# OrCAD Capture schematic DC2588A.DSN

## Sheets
1 PAGE2: size B; title: 18-Bit, 15Msps SAR ADC + Driver Amp; rev: 2; company: LTC2387CUH FAMILY; note: DEMO CIRCUIT 2588A; note: B
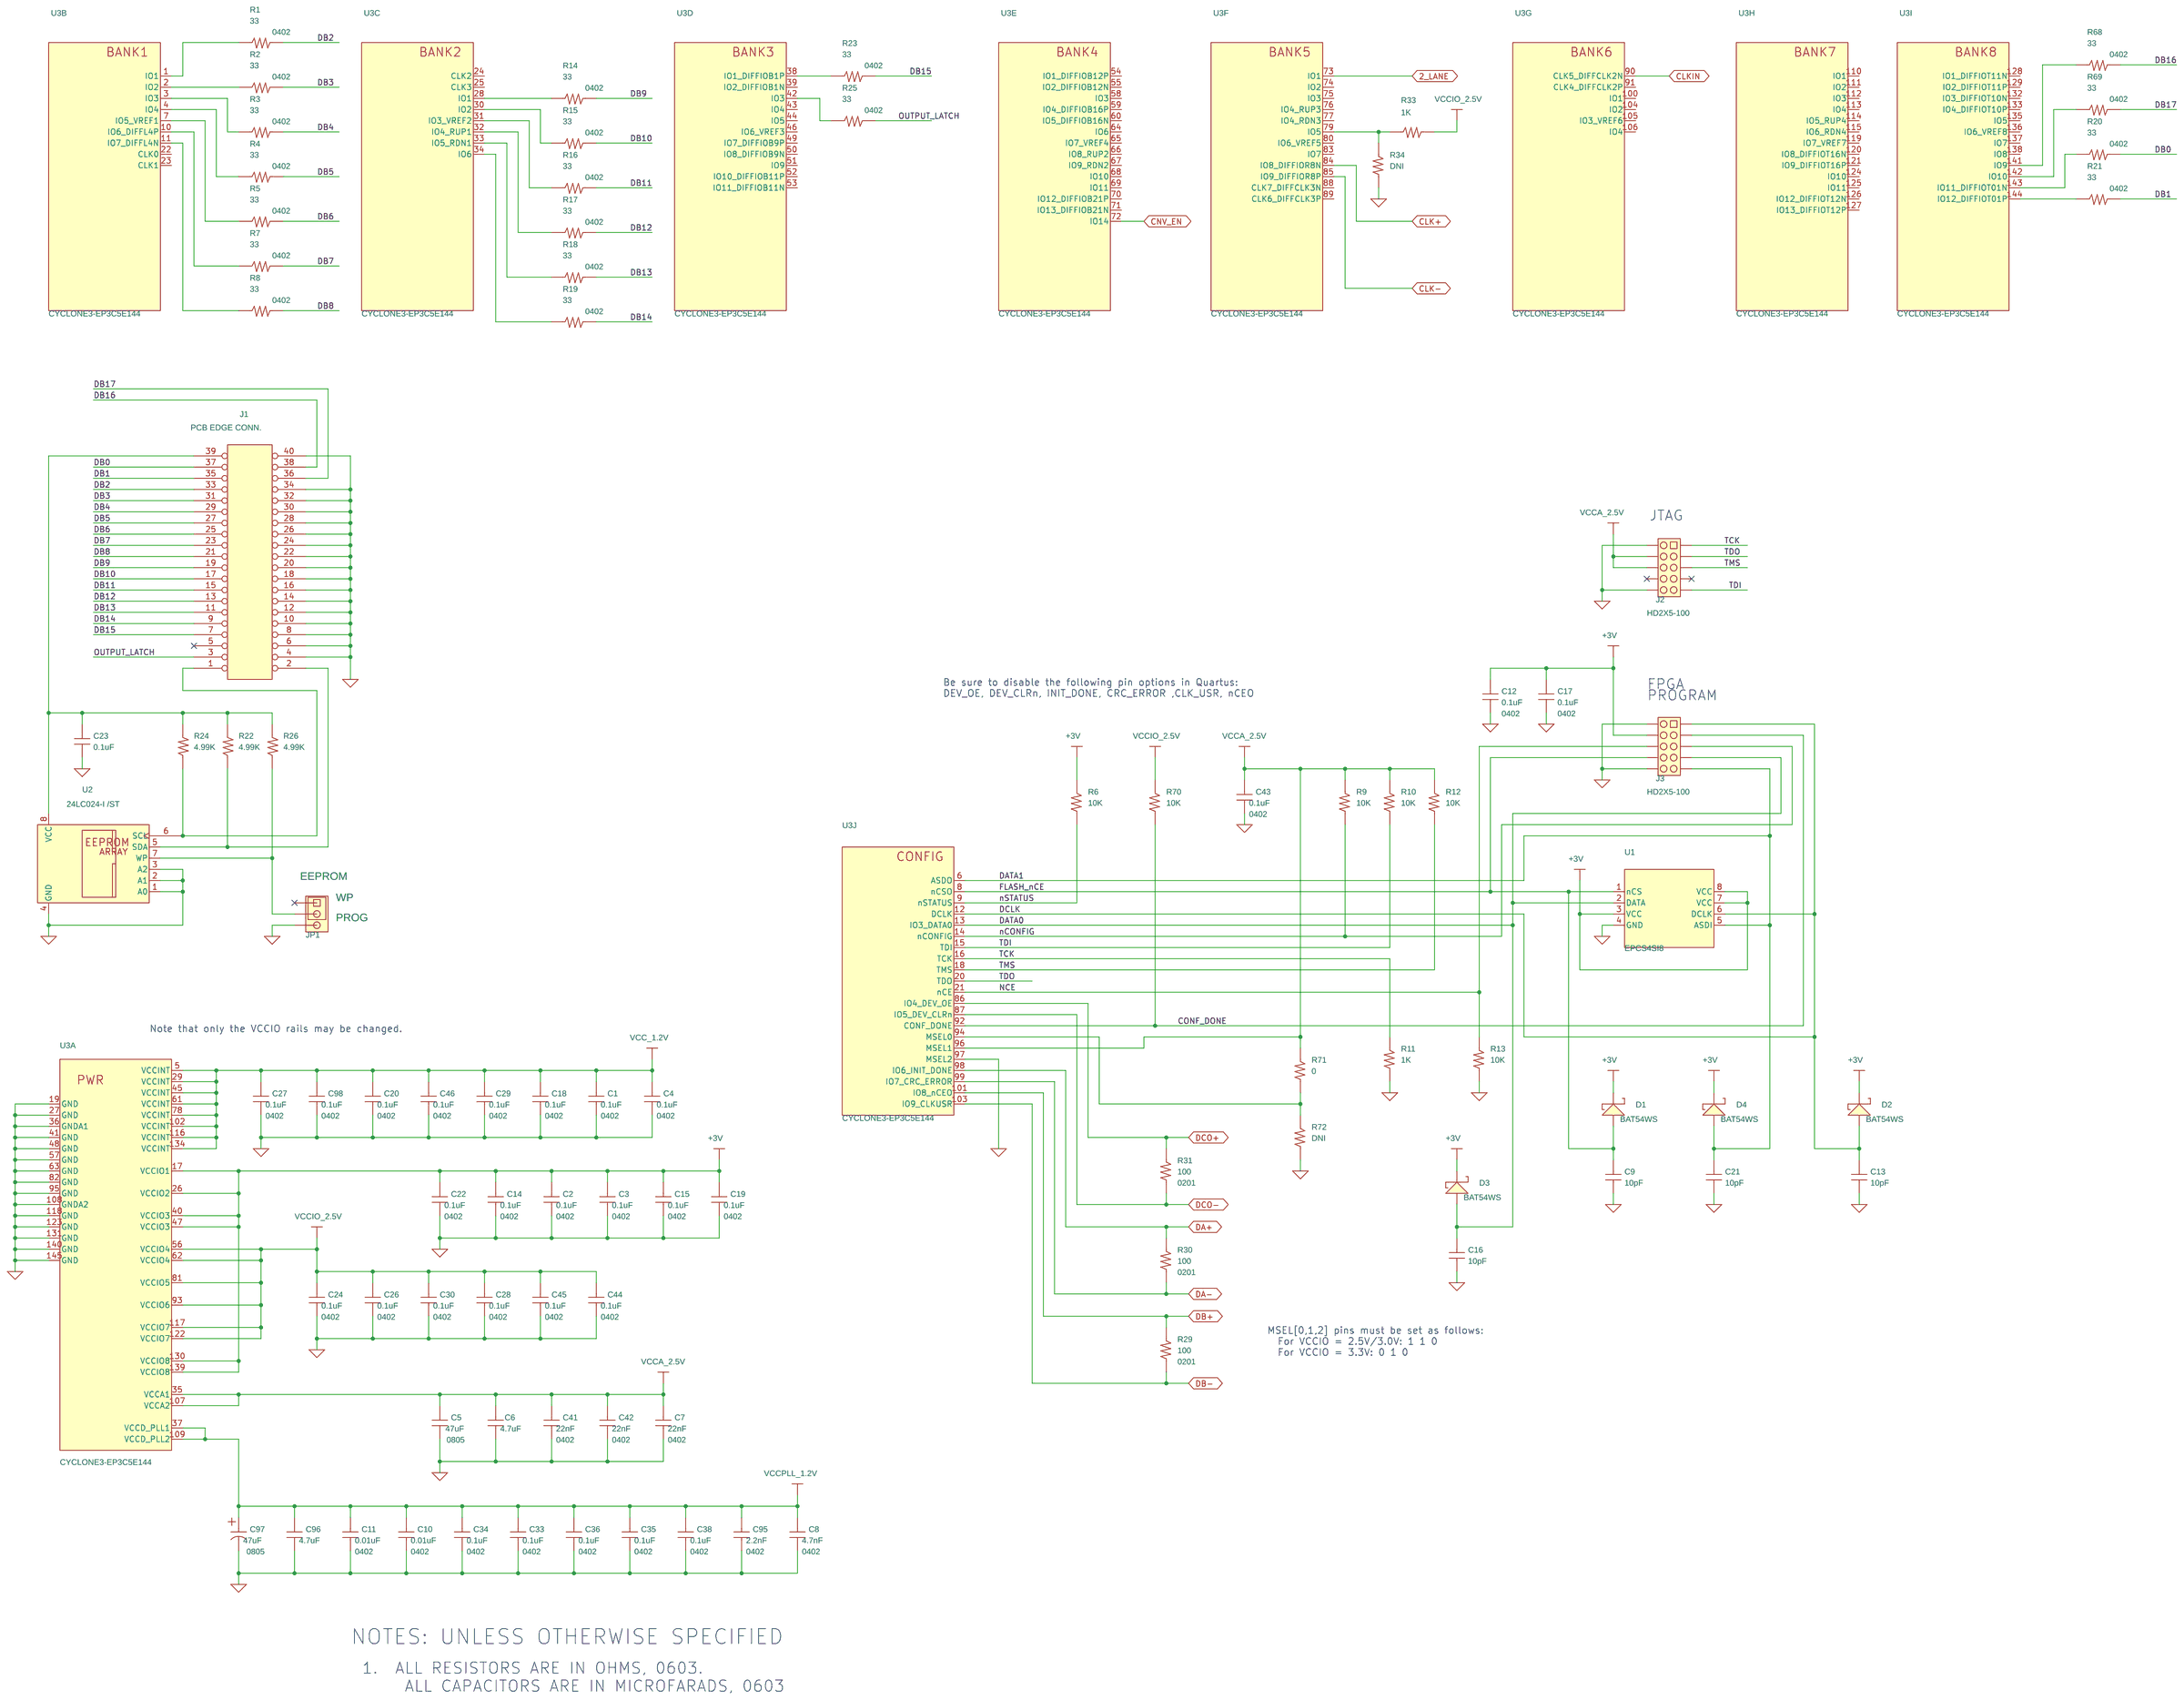
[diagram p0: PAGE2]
2 PAGE1: size B; rev: 1
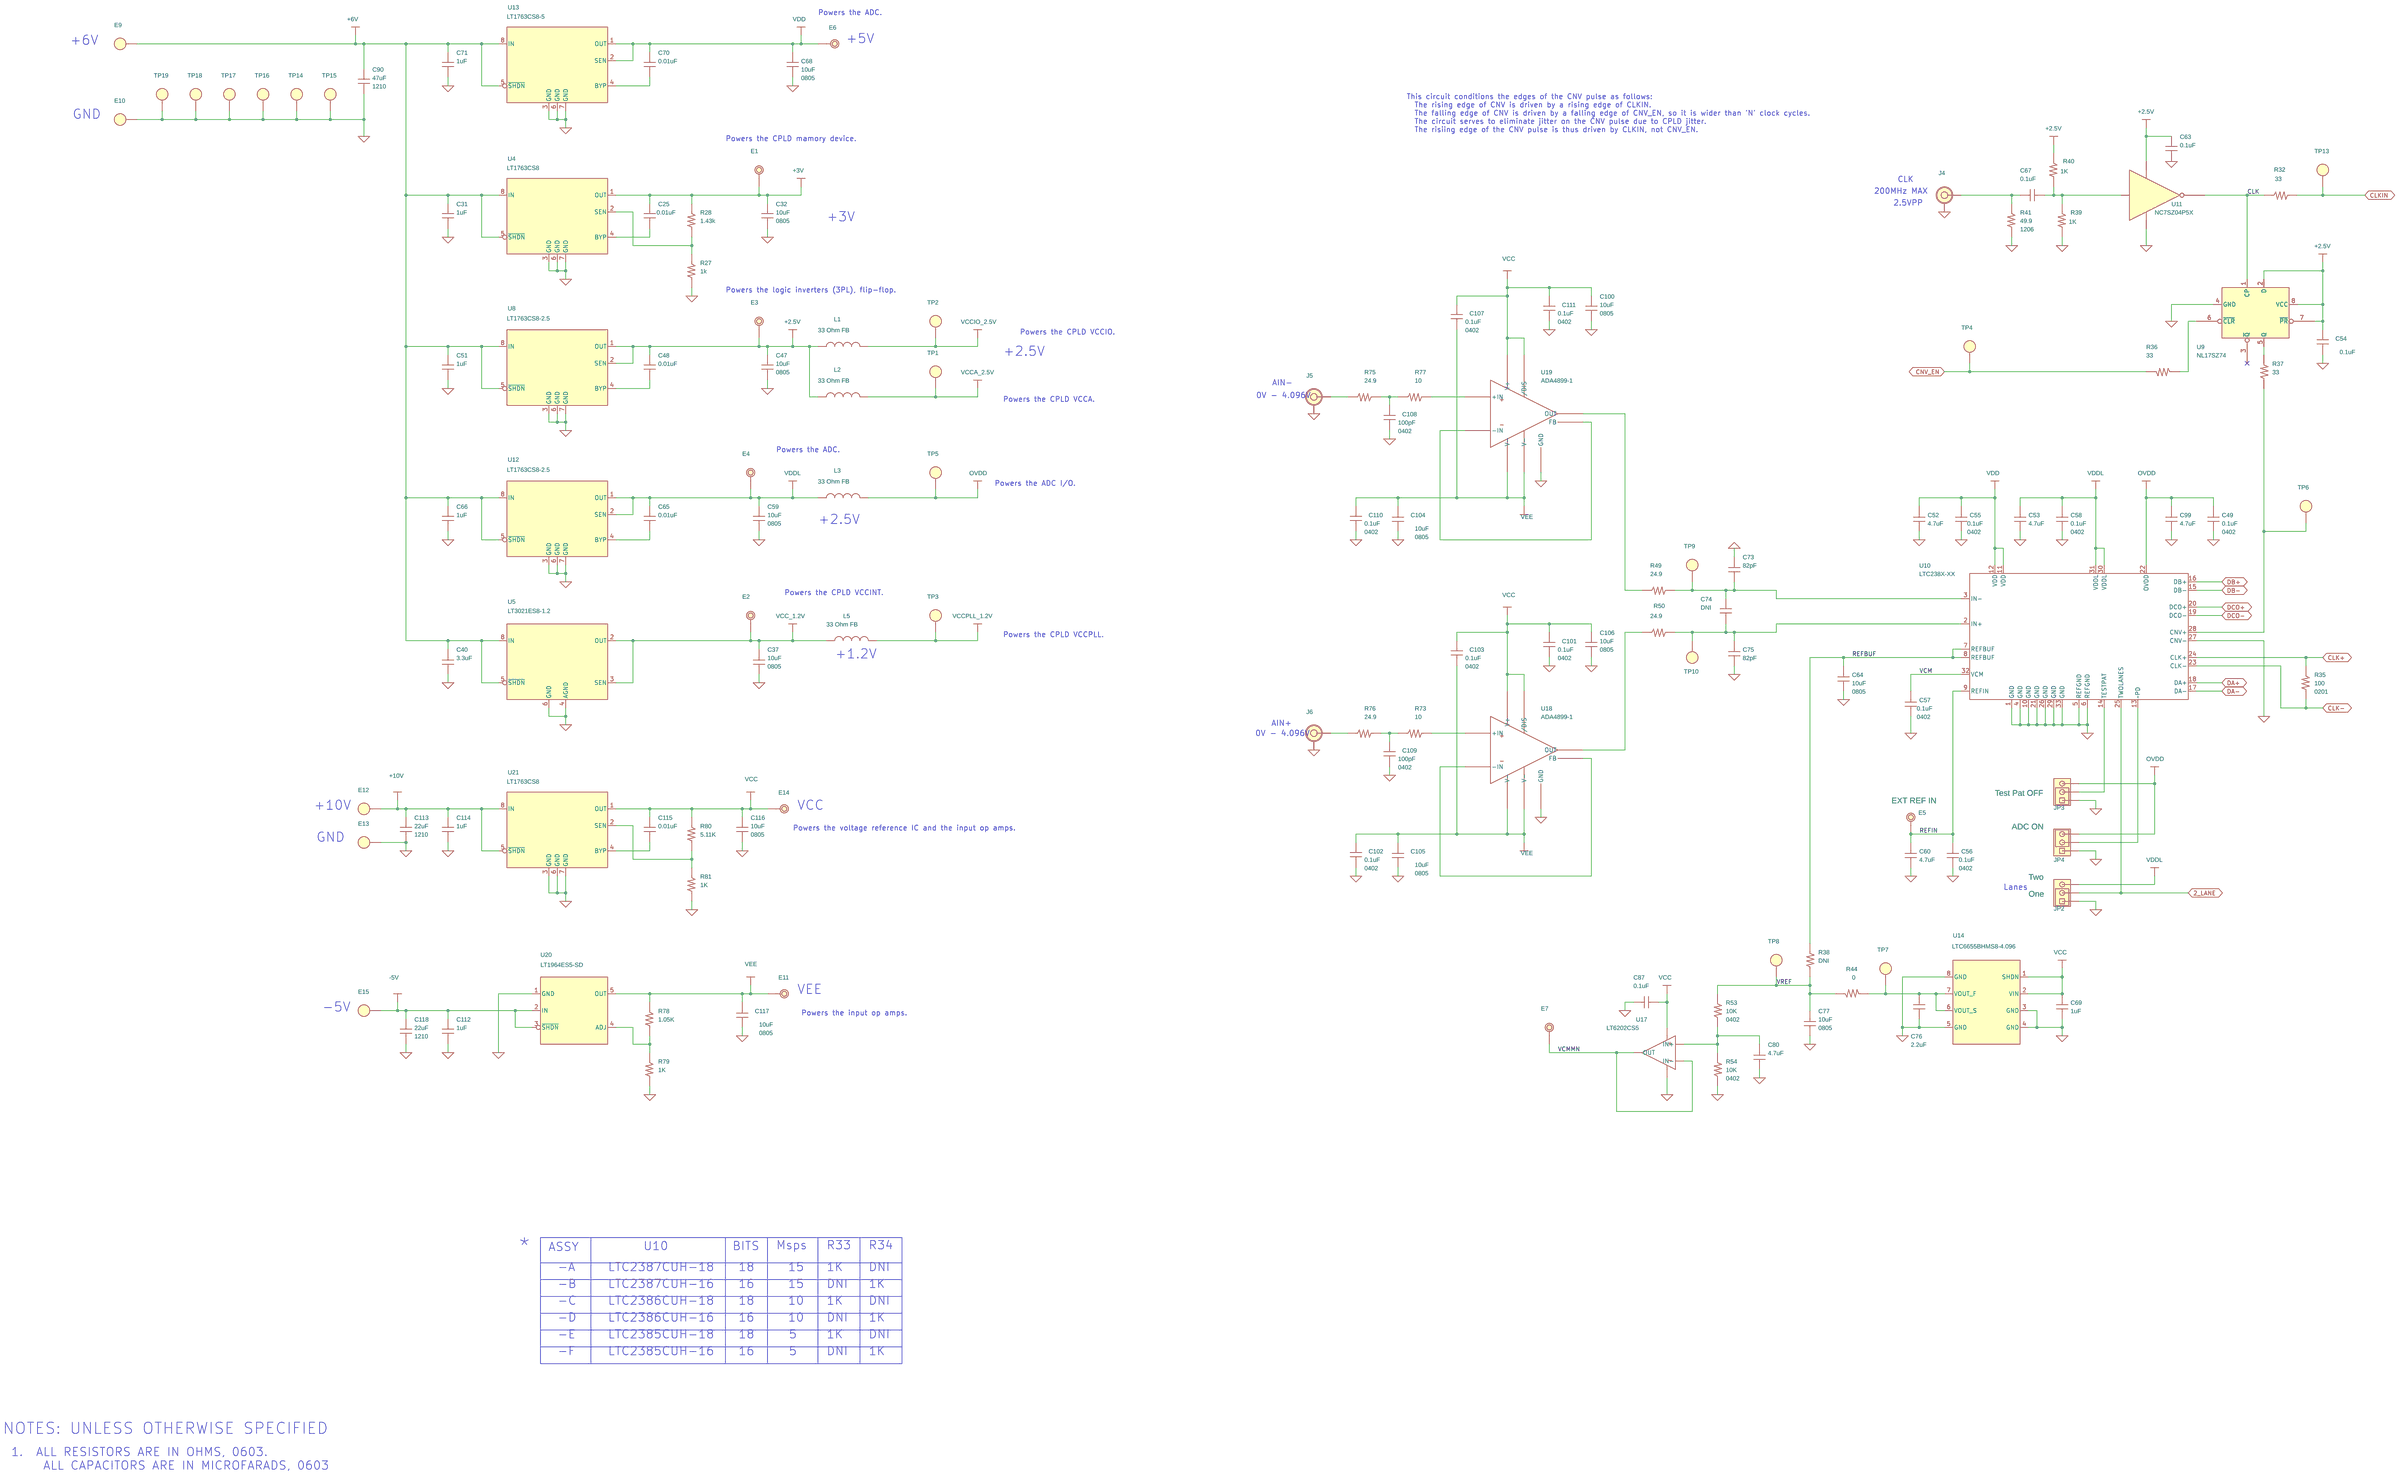
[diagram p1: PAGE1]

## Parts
sheet PAGE1
C25  0.01uF  [0603]
C31  1uF  [0603]
C32  10uF  [0805]
C37  10uF  [0805]
C40  3.3uF  [0603]
C47  10uF  [0805]
C48  0.01uF  [0603]
C49  0.1uF  [0402]
C51  1uF  [0603]
C52  4.7uF  [0603]
C53  4.7uF  [0603]
C54  0.1uF  [0603]
C55  0.1uF  [0402]
C56  0.1uF  [0402]
C57  0.1uF  [0402]
C58  0.1uF  [0402]
C59  10uF  [0805]
C60  4.7uF  [0603]
C63  0.1uF  [0603]
C64  10uF  [0805]
C65  0.01uF  [0603]
C66  1uF  [0603]
C67  0.1uF  [0603]
C68  10uF  [0805]
C69  1uF  [0603]
C70  0.01uF  [0603]
C71  1uF  [0603]
C73  82pF  [0603]
C74  DNI  [0603]
C75  82pF  [0603]
C76  2.2uF  [0603]
C77  10uF  [0805]
C80  4.7uF  [0603]
C87  0.1uF  [0603]
C90  47uF  [1210]
C99  4.7uF  [0603]
C100  10uF  [0805]
C101  0.1uF  [0402]
C102  0.1uF  [0402]
C103  0.1uF  [0402]
C104  10uF  [0805]
C105  10uF  [0805]
C106  10uF  [0805]
C107  0.1uF  [0402]
C108  100pF  [0402]
C109  100pF  [0402]
C110  0.1uF  [0402]
C111  0.1uF  [0402]
C112  1uF  [0603]
C113  22uF  [1210]
C114  1uF  [0603]
C115  0.01uF  [0603]
C116  10uF  [0805]
C117  10uF  [0805]
C118  22uF  [1210]
E1  MILL-MAX-2308  [MILL-MAX-2308]
E2  MILL-MAX-2308  [MILL-MAX-2308]
E3  MILL-MAX-2308  [MILL-MAX-2308]
E4  MILL-MAX-2308  [MILL-MAX-2308]
E5  MILL-MAX-2308  [MILL-MAX-2308]
E6  MILL-MAX-2308  [MILL-MAX-2308]
E7  MILL-MAX-2308  [MILL-MAX-2308]
E9  MIL-MAX-2501  [MILL-MAX-2501]
E10  MIL-MAX-2501  [MILL-MAX-2501]
E11  MILL-MAX-2308  [MILL-MAX-2308]
E12  MIL-MAX-2501  [MILL-MAX-2501]
E13  MIL-MAX-2501  [MILL-MAX-2501]
E14  MILL-MAX-2308  [MILL-MAX-2308]
E15  MIL-MAX-2501  [MILL-MAX-2501]
J4  BNC5  [BNC5]
J5  BNC5  [EFJOHNSON142-0701-851]
J6  BNC5  [EFJOHNSON142-0701-851]
JP2  HD1X3-100  [HD1X3-100]
JP3  HD1X3-100  [HD1X3-100]
JP4  HD1X3-100  [HD1X3-100]
L1  33 Ohm FB  [0603]
L2  33 Ohm FB  [0603]
L3  33 Ohm FB  [0603]
L5  33 Ohm FB  [0603]
R27  1k  [0603]
R28  1.43k  [0603]
R32  33  [0603]
R35  100  [0201]
R36  33  [0603]
R37  33  [0603]
R38  DNI  [0603]
R39  1K  [0603]
R40  1K  [0603]
R41  49.9  [1206]
R44  0  [0603]
R49  24.9  [0402]
R50  24.9  [0402]
R53  10K  [0402]
R54  10K  [0402]
R73  10  [0402]
R75  24.9  [0402]
R76  24.9  [0402]
R77  10  [0402]
R78  1.05K  [0603]
R79  1K  [0603]
R80  5.11K  [0603]
R81  1K  [0603]
TP1  TEST PIN, COPPER PAD 40/20  [TEST-PIN]
TP2  TEST PIN, COPPER PAD 40/20  [TEST-PIN]
TP3  TEST PIN, COPPER PAD 40/20  [TEST-PIN]
TP4  TEST PIN, COPPER PAD 40/20  [TEST-PIN]
TP5  TEST PIN, COPPER PAD 40/20  [TEST-PIN]
TP6  TEST PIN, COPPER PAD 40/20  [TEST-PIN]
TP7  TEST PIN, COPPER PAD 40/20  [TEST-PIN]
TP8  TEST PIN, COPPER PAD 40/20  [TEST-PIN]
TP9  TEST PIN, COPPER PAD 40/20  [TEST-PIN]
TP10  TEST PIN, COPPER PAD 40/20  [TEST-PIN]
TP13  TEST PIN, COPPER PAD 40/20  [TEST-PIN]
TP14  TEST PIN, COPPER PAD 40/20  [TEST-PIN]
TP15  TEST PIN, COPPER PAD 40/20  [TEST-PIN]
TP16  TEST PIN, COPPER PAD 40/20  [TEST-PIN]
TP17  TEST PIN, COPPER PAD 40/20  [TEST-PIN]
TP18  TEST PIN, COPPER PAD 40/20  [TEST-PIN]
TP19  TEST PIN, COPPER PAD 40/20  [TEST-PIN]
U4  LT1763CS8  [SO8]
U5  LT3021ES8-1.2  [SO8]
U8  LT1763CS8-2.5  [SO8]
U9  NL17SZ74  [US8]
U10  LTC238X-XX  [5X5QFN32]
U11  NC7SZ04P5X  [SC70-5]
U12  LT1763CS8-2.5  [SO8]
U13  LT1763CS8-5  [SO8]
U14  LTC6655BHMS8-4.096  [MSOP8]
U17  LT6202CS5  [TSOT23-5]
U18  ADA4899-1  [SO8_PADDLE]
U19  ADA4899-1  [SO8_PADDLE]
U20  LT1964ES5-SD  [SOT23-S5]
U21  LT1763CS8  [SO8]
sheet PAGE2
C1  0.1uF  [0402]
C2  0.1uF  [0402]
C3  0.1uF  [0402]
C4  0.1uF  [0402]
C5  47uF  [0805]
C6  4.7uF  [0603]
C7  22nF  [0402]
C8  4.7nF  [0402]
C9  10pF  [0402]
C10  0.01uF  [0402]
C11  0.01uF  [0402]
C12  0.1uF  [0402]
C13  10pF  [0402]
C14  0.1uF  [0402]
C15  0.1uF  [0402]
C16  10pF  [0402]
C17  0.1uF  [0402]
C18  0.1uF  [0402]
C19  0.1uF  [0402]
C20  0.1uF  [0402]
C21  10pF  [0402]
C22  0.1uF  [0402]
C23  0.1uF  [0603]
C24  0.1uF  [0402]
C26  0.1uF  [0402]
C27  0.1uF  [0402]
C28  0.1uF  [0402]
C29  0.1uF  [0402]
C30  0.1uF  [0402]
C33  0.1uF  [0402]
C34  0.1uF  [0402]
C35  0.1uF  [0402]
C36  0.1uF  [0402]
C38  0.1uF  [0402]
C41  22nF  [0402]
C42  22nF  [0402]
C43  0.1uF  [0402]
C44  0.1uF  [0402]
C45  0.1uF  [0402]
C46  0.1uF  [0402]
C95  2.2nF  [0402]
C96  4.7uF  [0603]
C97  47uF  [0805]
C98  0.1uF  [0402]
D1  BAT54WS  [SOD323]
D2  BAT54WS  [SOD323]
D3  BAT54WS  [SOD323]
D4  BAT54WS  [SOD323]
J1  PCB EDGE CONN.  [HD2X20-100SMT-TB]
J2  HD2X5-100  [HD2X5-100]
J3  HD2X5-100  [HD2X5-100]
JP1  HD1X3-100  [HD1X3-100]
R1  33  [0402]
R2  33  [0402]
R3  33  [0402]
R4  33  [0402]
R5  33  [0402]
R6  10K  [0402]
R7  33  [0402]
R8  33  [0402]
R9  10K  [0402]
R10  10K  [0402]
R11  1K  [0402]
R12  10K  [0402]
R13  10K  [0402]
R14  33  [0402]
R15  33  [0402]
R16  33  [0402]
R17  33  [0402]
R18  33  [0402]
R19  33  [0402]
R20  33  [0402]
R21  33  [0402]
R22  4.99K  [0603]
R23  33  [0402]
R24  4.99K  [0603]
R25  33  [0402]
R26  4.99K  [0603]
R29  100  [0201]
R30  100  [0201]
R31  100  [0201]
R33  1K  [0402]
R34  DNI  [0402]
R68  33  [0402]
R69  33  [0402]
R70  10K  [0402]
R71  0  [0402]
R72  DNI  [0402]
U1  EPCS4SI8  [SO8]
U2  24LC024-I /ST  [TSSOP8]
U3  CYCLONE3-EP3C5E144  [EQFP144]  (sections A,B,C,D,E,F,G,H,I,J)

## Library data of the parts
C1-C30 C33-C38 C40-C46 C48 C49 C52-C58 C60 C63-C65 C67-C70 C74 C76 C77 C80 C87 C95 C96 C98-C111 C115-C117 = CAP-NP
C31 C51 C66 C71 C90 C112-C114 C118 = CAP-NP: 1ST PART FIELD: 16V
C32 C47 C59 = CAP-NP: 1ST PART FIELD: 6.3V
C73 C75 = CAP-NP: OPT: OPT
E1-E4 E6 E7 E11 E14 = E-064
E5 = E-064: 1st Part Field: EXT REF IN
E9 E10 E12 E13 E15 = E-094
J4-J6 = BNC
JP2 = HD1X3: 1st Part Field: CM1; 2nd Part Field: Two; 3rd Part Field: One
JP3 = HD1X3: 1st Part Field: CM1; 2nd Part Field: Normal Operation; 3rd Part Field: Test Pat OFF
JP4 = HD1X3_0: 1st Part Field: CM1; 2nd Part Field: EXT; 3rd Part Field: ADC ON
L1-L3 L5 = IND: FERRITE BEAD, 1206; Part Number: MURATA BLM31PG330SN1L
R1-R37 R39-R41 R44 R49 R50 R53 R54 R68-R73 R75-R81 = R
R38 = R: OPT: OPT
TP1-TP10 TP13-TP19 = TEST_PIN,_COPPER_PAD_40_20
U4 U8 U12 U13 U21 = LT1763CS8-SO8
U5 = LT3021ES8-SO8
U9 = NL17SZ74-US8
U10 = LTC23XXCUFD-QFN28UFD-4X5_0: 1st Part Field: *
U11 = NC7SZ04P5X-ONE
U14 = LTC6655AHMSH-5
U17 = LT6202CS5-TSOT23
U18 U19 = 5962-9313001_3
U20 = LT1964ES5-SD-SOT23-5
C97 = CAP
D1-D4 = BAT54WS-SOD323
J1 = EDGE_FINGERS,_2X20-0.100: Package: <Package>
J2 J3 = HD2X5-100_0
JP1 = HD1X3: 1st Part Field: EEPROM; 2nd Part Field: PROG; 3rd Part Field: WP
U1 = EPCS4SI8-SO8_0
U2 = 24LC025-I_ST
U3 = CYCLONE3-EP3C5E144-EQFP144_8

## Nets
+2.5V: C47.1 C48.1 C54.1 C63.1 E3.1(A) L1.1 L2.1 R40.1 U8.1(OUT) U8.2(SEN) U9.2(D) U9.7(~{PR}) U9.8(VCC) U11.5
+3V: C2.2 C3.2 C12.2 C14.2 C15.2 C17.2 C19.2 C22.2 C25.1 C32.1 D1.1 D2.1 D3.1 D4.1 E1.1(A) J3.4 R6.1 R28.1 U1.3(VCC) U1.7(VCC) U1.8(VCC) U3.17(VCCIO1) U3.26(VCCIO2) U3.40(VCCIO3) U3.47(VCCIO3) U3.130(VCCIO8) U3.139(VCCIO8) U4.1(OUT)
+6V: C31.1 C40.2 C51.1 C66.1 C71.1 C90.1 E9.1(A) U4.5(~{SHDN}) U4.8(IN) U5.5(~{SHDN}) U5.8(IN) U8.5(~{SHDN}) U8.8(IN) U12.5(~{SHDN}) U12.8(IN) U13.5(~{SHDN}) U13.8(IN)
+10V: C113.1 C114.1 E12.1(A) U21.5(~{SHDN}) U21.8(IN)
-5V: C112.1 C118.1 E15.1(A) U20.2(IN) U20.3(~{SHDN})
GND: C1.1 C2.1 C3.1 C4.1 C5.1 C6.1 C7.1 C8.1 C9.1 C10.1 C11.1 C12.1 C13.1 C14.1 C15.1 C16.1 C17.1 C18.1 C19.1 C20.1 C21.1 C22.1 C23.1 C24.1 C26.1 C27.1 C28.1 C29.1 C30.1 C31.2 C32.2 C33.1 C34.1 C35.1 C36.1 C37.1 C38.1 C40.1 C41.1 C42.1 C43.1 C44.1 C45.1 C46.1 C47.2 C49.1 C51.2 C52.1 C53.1 C54.2 C55.1 C56.1 C57.1 C58.1 C59.2 C60.1 C63.2 C64.1 C66.2 C68.2 C69.1 C71.2 C73.2 C75.1 C76.1 C77.1 C80.1 C87.2 C90.2 C95.1 C96.1 C97.2 C98.1 C99.1 C100.2 C101.2 C102.2 C104.1 C105.1 C106.2 C108.2 C109.2 C110.2 C111.2 C112.2 C113.2 C114.2 C116.2 C117.1 C118.2 E10.1(A) E13.1(A) J1.4 J1.6 J1.8 J1.10 J1.12 J1.14 J1.16 J1.18 J1.20 J1.22 J1.24 J1.26 J1.28 J1.30 J1.32 J1.34 J1.40 J2.2 J2.10 J3.2 J3.10 J4.2 J4.3 J4.4 J4.5 J5.2 J5.3 J5.4 J5.5 J6.2 J6.3 J6.4 J6.5 JP1.3 JP2.1 JP3.1 JP4.1 R11.2 R13.2 R27.2 R34.2 R39.2 R41.2 R54.1 R72.2 R79.2 R81.2 TP14.1(A) TP15.1(A) TP16.1(A) TP17.1(A) TP18.1(A) TP19.1(A) U1.4(GND) U2.1(A0) U2.2(A1) U2.3(A2) U2.4(GND) U3.19(GND) U3.27(GND) U3.36(GNDA1) U3.41(GND) U3.48(GND) U3.57(GND) U3.63(GND) U3.82(GND) U3.95(GND) U3.97(MSEL2) U3.108(GNDA2) U3.118(GND) U3.123(GND) U3.131(GND) U3.140(GND) U3.145(GND) U4.3(GND) U4.6(GND) U4.7(GND) U5.4(AGND) U5.6(GND) U8.3(GND) U8.6(GND) U8.7(GND) U9.4(GND) U10.1(GND) U10.4(GND) U10.5(REFGND) U10.6(REFGND) U10.10(GND) U10.21(GND) U10.26(GND) U10.27(CNV-) U10.29(GND) U10.33(GND) U11.3 U12.3(GND) U12.6(GND) U12.7(GND) U13.3(GND) U13.6(GND) U13.7(GND) U14.3(GND) U14.4(GND) U14.5(GND) U14.8(GND) U17.2 U18.9(GND) U19.9(GND) U20.1(GND) U21.3(GND) U21.6(GND) U21.7(GND)
VCC: C69.2 C87.1 C100.1 C101.1 C103.1 C106.1 C107.1 C111.1 C115.1 C116.1 E14.1(A) R80.1 U14.1(SHDN) U14.2(VIN) U17.5 U18.7(V+) U18.8(/DIS) U19.7(V+) U19.8(/DIS) U21.1(OUT)
VCC_1.2V: C1.2 C4.2 C18.2 C20.2 C27.2 C29.2 C37.2 C46.2 C98.2 E2.1(A) L5.2 U3.5(VCCINT) U3.29(VCCINT) U3.45(VCCINT) U3.61(VCCINT) U3.78(VCCINT) U3.102(VCCINT) U3.116(VCCINT) U3.134(VCCINT) U5.2(OUT) U5.3(SEN)
VCCA_2.5V: C5.2 C6.2 C7.2 C41.2 C42.2 C43.2 J2.4 J2.6 L2.2 R9.1 R10.1 R12.1 R71.1 TP1.1(A) U3.35(VCCA1) U3.96(MSEL1) U3.107(VCCA2)
VCCIO_2.5V: C24.2 C26.2 C28.2 C30.2 C44.2 C45.2 L1.2 R33.2 R70.1 TP2.1(A) U3.56(VCCIO4) U3.62(VCCIO4) U3.81(VCCIO5) U3.93(VCCIO6) U3.117(VCCIO7) U3.122(VCCIO7)
VCCPLL_1.2V: C8.2 C10.2 C11.2 C33.2 C34.2 C35.2 C36.2 C38.2 C95.2 C96.2 C97.1 L5.1 TP3.1(A) U3.37(VCCD_PLL1) U3.109(VCCD_PLL2)
VDD: C52.2 C55.2 C68.1 C70.1 E6.1(A) U10.11(VDD) U10.12(VDD) U13.1(OUT) U13.2(SEN)
VDDL: C53.2 C58.2 C59.1 C65.1 E4.1(A) JP2.3 L3.1 U10.30(VDDL) U10.31(VDDL) U12.1(OUT) U12.2(SEN)
VEE: C102.1 C103.2 C104.2 C105.2 C107.2 C110.1 C117.2 E11.1(A) R78.1 U18.4(V-) U18.5(V-) U19.4(V-) U19.5(V-) U20.5(OUT)
2_LANE: JP2.2 U3.73(IO1) U10.25(TWOLANES)
CLK: R32.1 U9.1(CP) U11.4
CLK+: R35.1 U3.84(IO8_DIFFIOR8N) U10.24(CLK+)
CLK-: R35.2 U3.85(IO9_DIFFIOR8P) U10.23(CLK-)
CLKIN: R32.2 TP13.1(A) U3.90(CLK5_DIFFCLK2N)
CNV_EN: R36.2 TP4.1(A) U3.72(IO14)
CONF_DONE: J3.3 R70.2 U3.92(CONF_DONE)
DA+: R30.1 U3.98(IO6_INIT_DONE) U10.18(DA+)
DA-: R30.2 U3.99(IO7_CRC_ERROR) U10.17(DA-)
DATA0: C16.2 D3.2 J3.7 U1.2(DATA) U3.13(IO3_DATA0)
DATA1: C21.2 D4.2 J3.9 U1.5(ASDI) U3.6(ASDO)
DB0: J1.37 R20.2
DB1: J1.35 R21.2
DB2: J1.33 R1.2
DB3: J1.31 R2.2
DB4: J1.29 R3.2
DB5: J1.27 R4.2
DB6: J1.25 R5.2
DB7: J1.23 R7.2
DB8: J1.21 R8.2
DB9: J1.19 R14.2
DB10: J1.17 R15.2
DB11: J1.15 R16.2
DB12: J1.13 R17.2
DB13: J1.11 R18.2
DB14: J1.9 R19.2
DB15: J1.7 R23.2
DB16: J1.38 R68.2
DB17: J1.36 R69.2
DB+: R29.1 U3.101(IO8_nCEO) U10.16(DB+)
DB-: R29.2 U3.103(IO9_CLKUSR) U10.15(DB-)
DCLK: C13.2 D2.2 J3.1 U1.6(DCLK) U3.12(DCLK)
DCO+: R31.1 U3.86(IO4_DEV_OE) U10.20(DCO+)
DCO-: R31.2 U3.87(IO5_DEV_CLRn) U10.19(DCO-)
FLASH_nCE: C9.2 D1.2 J3.8 U1.1(nCS) U3.8(nCSO)
NCE: J3.6 R13.1 U3.21(nCE)
nCONFIG: J3.5 R9.2 U3.14(nCONFIG)
nSTATUS: R6.2 U3.9(nSTATUS)
OUTPUT_LATCH: J1.3 R25.2
OVDD: C49.2 C99.2 JP3.3 JP4.3 L3.2 TP5.1(A) U10.22(OVDD)
REFBUF: C64.2 R38.2 U10.7(REFBUF) U10.8(REFBUF)
REFIN: C56.2 C60.2 E5.1(A) U10.9(REFIN)
TCK: J2.1 R11.1 U3.16(TCK)
TDI: J2.9 R10.2 U3.15(TDI)
TDO: J2.3 U3.20(TDO)
TMS: J2.5 R12.2 U3.18(TMS)
VCM: C57.2 U10.32(VCM)
VCMMN: E7.1(A) U17.1(OUT) U17.4(IN-)
VREF: C77.2 R38.1 R44.1 R53.2 TP8.1(A)
N928027: C67.2 R39.1 R40.2 U11.2
N928109: C67.1 J4.1 R41.1
N932409: R37.2 U9.5(Q)
N2695300: C74.2 C75.2 R50.2 TP10.1(A) U10.2(IN+)
N2752563: C73.1 C74.1 R49.2 TP9.1(A) U10.3(IN-)
N2978849: R37.1 TP6.1(A) U10.28(CNV+)
N3254403: C23.2 J1.39 R22.2 R24.2 R26.2 U2.8(VCC)
N3256316: J1.2 R22.1 U2.5(SDA)
N3257128: J1.1 R24.1 U2.6(SCL)
N3257370: JP1.2 R26.1 U2.7(WP)
N4561890: C76.2 R44.2 TP7.1(A) U14.6(VOUT_S) U14.7(VOUT_F)
N4562258: C80.2 R53.1 R54.2 U17.3(IN+)
N5068666: R33.1 R34.1 U3.79(IO5)
N5944249: JP3.2 U10.14(TESTPAT)
N5944372: JP4.2 U10.13(~PD)
N5995540: R68.1 U3.141(IO9)
N5995618: R21.1 U3.144(IO12_DIFFIOT01P)
N5995628: R20.1 U3.143(IO11_DIFFIOT01N)
N6148031: R4.1 U3.4(IO4)
N6148318: R3.1 U3.3(IO3)
N6171846: R1.1 U3.1(IO1)
N6171932: R2.1 U3.2(IO2)
N6172448: R7.1 U3.10(IO6_DIFFL4P)
N6172514: R8.1 U3.11(IO7_DIFFL4N)
N6173228: R16.1 U3.31(IO3_VREF2)
N6173232: R14.1 U3.28(IO1)
N6173236: R19.1 U3.34(IO6)
N6173240: R15.1 U3.30(IO2)
N6173258: R17.1 U3.32(IO4_RUP1)
N6173683: R23.1 U3.38(IO1_DIFFIOB1P)
N6173823: R25.1 U3.42(IO3)
N6175421: R69.1 U3.142(IO10)
N6206059: R5.1 U3.7(IO5_VREF1)
N6206524: R18.1 U3.33(IO5_RDN1)
N6324668: R71.2 R72.1 U3.94(MSEL0)
N6363440: R36.1 U9.6(~{CLR})
N6407261: C48.2 U8.4(BYP)
N6407317: R27.1 R28.2 U4.2(SEN)
N6407557: C70.2 U13.4(BYP)
N6407735: C25.2 U4.4(BYP)
N6407739: C65.2 U12.4(BYP)
N6464773: U18.1(FB) U18.2(-IN)
N6464839: R73.2 U18.3(+IN)
N6464881: R50.1 U18.6(OUT)
N6465313: C108.1 R75.2 R77.1
N6465317: J5.1 R75.1
N6465321: C109.1 R73.1 R76.2
N6465325: J6.1 R76.1
N6465445: R49.1 U19.6(OUT)
N6465471: R77.2 U19.3(+IN)
N6465537: U19.1(FB) U19.2(-IN)
N6475172: R78.2 R79.1 U20.4(ADJ)
N6475200: R80.2 R81.1 U21.2(SEN)
N6475624: C115.2 U21.4(BYP)

Not connected (* = marked no-connect by the designer): J1 5*; J2 7* 8*; JP1 1*; U3 22(CLK0) 23(CLK1) 24(CLK2) 25(CLK3) 39(IO2_DIFFIOB1N) 43(IO4) 44(IO5) 46(IO6_VREF3) 49(IO7_DIFFIOB9P) 50(IO8_DIFFIOB9N) 51(IO9) 52(IO10_DIFFIOB11P) 53(IO11_DIFFIOB11N) 54(IO1_DIFFIOB12P) 55(IO2_DIFFIOB12N) 58(IO3) 59(IO4_DIFFIOB16P) 60(IO5_DIFFIOB16N) 64(IO6) 65(IO7_VREF4) 66(IO8_RUP2) 67(IO9_RDN2) 68(IO10) 69(IO11) 70(IO12_DIFFIOB21P) 71(IO13_DIFFIOB21N) 74(IO2) 75(IO3) 76(IO4_RUP3) 77(IO4_RDN3) 80(IO6_VREF5) 83(IO7) 88(CLK7_DIFFCLK3N) 89(CLK6_DIFFCLK3P) 91(CLK4_DIFFCLK2P) 100(IO1) 104(IO2) 105(IO3_VREF6) 106(IO4) 110(IO1) 111(IO2) 112(IO3) 113(IO4) 114(IO5_RUP4) 115(IO6_RDN4) 119(IO7_VREF7) 120(IO8_DIFFIOT16N) 121(IO9_DIFFIOT16P) 124(IO10) 125(IO11) 126(IO12_DIFFIOT12N) 127(IO13_DIFFIOT12P) 128(IO1_DIFFIOT11N) 129(IO2_DIFFIOT11P) 132(IO3_DIFFIOT10N) 133(IO4_DIFFIOT10P) 135(IO5) 136(IO6_VREF8) 137(IO7) 138(IO8); U9 3(~{Q})*

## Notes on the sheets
sheet 1
- JTAG
- Be sure to disable the following pin options in Quartus:
  DEV_OE, DEV_CLRn, INIT_DONE, CRC_ERROR ,CLK_USR, nCEO
- FPGA
- PROGRAM
- Note that only the VCCIO rails may be changed.
- MSEL[0,1,2] pins must be set as follows:
    For VCCIO = 2.5V/3.0V: 1 1 0
    For VCCIO = 3.3V: 0 1 0
- NOTES: UNLESS OTHERWISE SPECIFIED
- 1.  ALL RESISTORS ARE IN OHMS, 0603.
       ALL CAPACITORS ARE IN MICROFARADS, 0603
sheet 2
- Powers the ADC.
- +6V
- +5V
- This circuit conditions the edges of the CNV pulse as follows:
    The rising edge of CNV is driven by a rising edge of CLKIN.
    The falling edge of CNV is driven by a falling edge of CNV_EN, so it is wider than 'N' clock cycles.
    The circuit serves to eliminate jitter on the CNV pulse due to CPLD jitter.
    The risiing edge of the CNV pulse is thus driven by CLKIN, not CNV_EN.
- GND
- Powers the CPLD mamory device.
- CLK
- 200MHz MAX
- 2.5VPP
- +3V
- Powers the logic inverters (3PL), flip-flop.
- Powers the CPLD VCCIO.
- +2.5V
- AIN-
- 0V - 4.096V
- Powers the CPLD VCCA.
- Powers the ADC.
- Powers the ADC I/O.
- +2.5V
- Powers the CPLD VCCINT.
- Powers the CPLD VCCPLL.
- +1.2V
- AIN+
- 0V - 4.096V
- +10V
- VCC
- Powers the voltage reference IC and the input op amps.
- GND
- Lanes
- VEE
- -5V
- Powers the input op amps.
- *
- ASSY
- U10
- BITS
- Msps
- R33
- R34
- -A
- LTC2387CUH-18
- 18
- 15
- 1K
- DNI
- -B
- LTC2387CUH-16
- 16
- 15
- DNI
- 1K
- -C
- LTC2386CUH-18
- 18
- 10
- 1K
- DNI
- -D
- LTC2386CUH-16
- 16
- 10
- DNI
- 1K
- -E
- LTC2385CUH-18
- 18
- 5
- 1K
- DNI
- -F
- LTC2385CUH-16
- 16
- 5
- DNI
- 1K
- NOTES: UNLESS OTHERWISE SPECIFIED
- 1.  ALL RESISTORS ARE IN OHMS, 0603.
       ALL CAPACITORS ARE IN MICROFARADS, 0603
